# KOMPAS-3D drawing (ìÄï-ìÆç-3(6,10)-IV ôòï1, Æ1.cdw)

Views: Вид 1, Спереди 2, Проекционный вид 3, Спереди 4, Проекционный вид 5, Проекционный вид 6, Проекционный вид 7, Проекционный вид 8, Проекционный вид 9, Изометрия XYZ 10, Вид 11, Вид 12, Вид 13, Спереди 14, Проекционный вид 15, Проекционный вид 16, Проекционный вид 17, Проекционный вид 18, Проекционный вид 19, Изометрия XYZ 20, Проекционный вид 22, Проекционный вид 23, Проекционный вид 25, Вид 26, Вид 27, Вид 28
Referenced files: GRAPHIC.TDP
Referenced files in Y:\Технический отдел\КБ\Рабочая папка\КД\Тр-ры наружной установки\Тр-ры силовые\ОЛ-НТЗ-6(10)-IV УХЛ1 от 25.10.14\Чертежи\: Трансформатор ОЛ  НТЗ.24.01.00.00.000 ГЧ.cdw
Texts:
  Body Specificaton ( centered )
  Body Specification ( left align )
  Title Specification
  Материал-Предприятие
  Лит-Масса-Масштаб
  Болт М10
  Крышка
  защитная
  Табличка технических
  данных
  Ввод кабельный М25
  max
  Контакт
  заземления
  Винт пломбировочный
  Трансформатор напряжения НОЛ-НТЗ-6(10)-IV УХЛ1
  Масса, не более, 38,5 кг
  Защитная крышка условно не показана
  Винт М6
  Шайба A. 6.37 ГОСТ 11371-78
  Шайба
  .Ти9
  ГОСТ
  АД1 ГОСТ 4784-97
  Шайба 6 Л ГОСТ 6402-70
  Шайба пружинная
  Винт А.М 4-6g x 35-22 ГОСТ 1491-80
  Винт обычный
  Винт
  Винт А.М 6-6g x 10 ГОСТ 1491-80
  Шайба210 Л ГОСТ 6402-70
  Болт М10-6g x 10 ГОСТ 7796-70
  Болт
  Шайба A. 10.37 ГОСТ 11371-78
  Поз.
  Кол.
  Приме-
  чание
  Таблица спецификации
  Трансформатор силовой малой мощности
  ОЛ-НТЗ-1,25/6(10)-IV УХЛ1, Т1
  Габаритный чертеж
  М.контр.
  НТЗ
  Михайлов
  Пимурзин
  Морозов
  Бадулин
  Фролова
  НТЗ.24.01.00.00.000
  Без внутренней рамки.
Dimensions and other numbers on the sheet: 2 шт.; 347; 236; 408; 418; 120; 190; 10; 4 отв.; 96; 54; 368; 176,5; 4 шт.; 25; 38; 28; 45; 4; 1; 78; 65Г; 029; 70; -6g; -22; 80; 2; 38,5; 1:4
